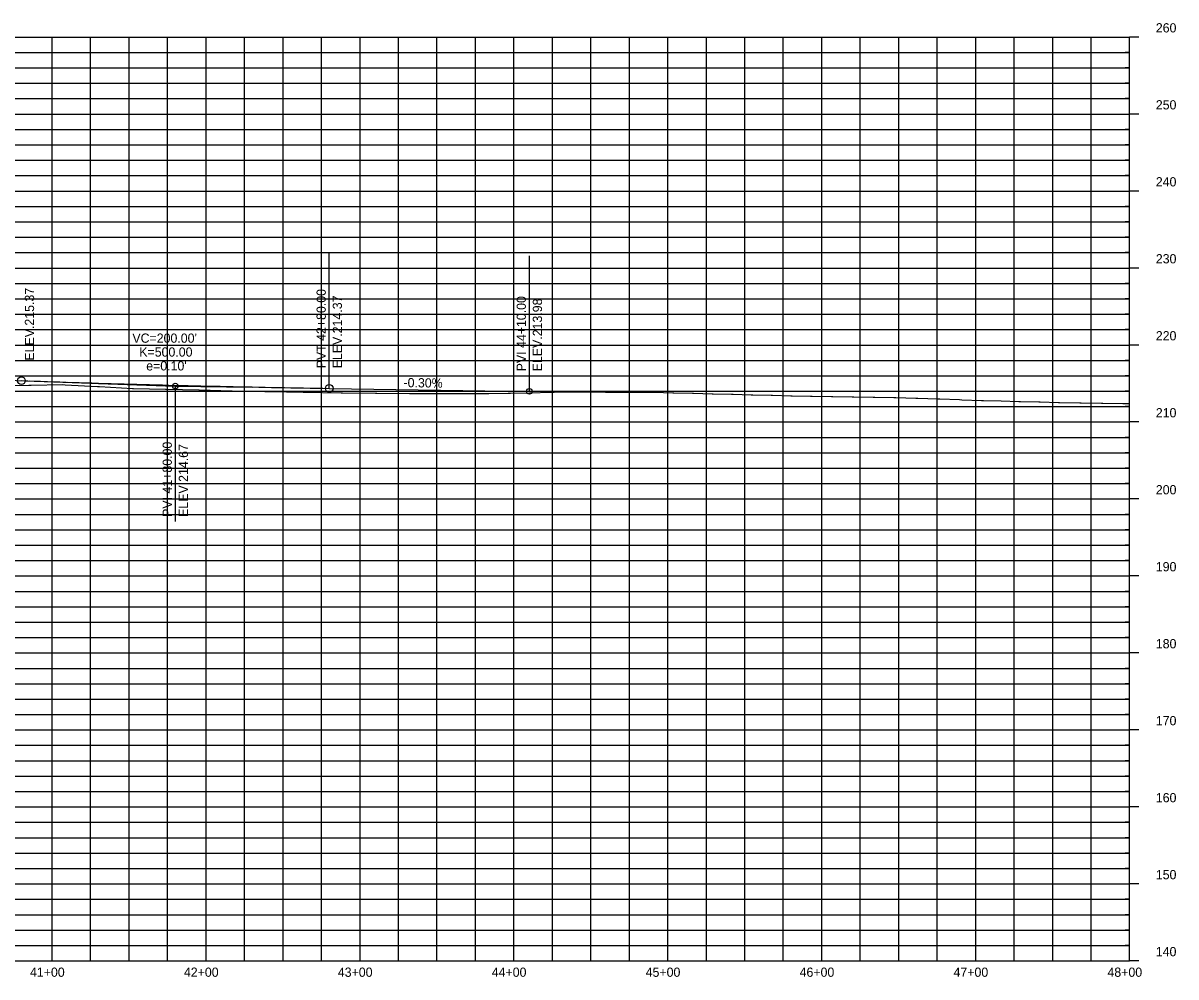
# Model space of a CAD drawing. Extents: x 1732967 to 1742744, y 374025 to 374739.
# Drawn here: x 1741995 to 1742744, y 374119 to 374739 of the extents above; entities that cross this region are included whole.
import ezdxf

# ---------------------------------------------------------------- set-up
doc = ezdxf.new("R2010")
doc.units = 0
for name, color, linetype in [('R_Axis_Annotation', 7, 'Continuous'), ('R_Exist Surface', 7, 'Continuous'), ('R_Grid', 7, 'Continuous'), ('R_Grid Annot', 7, 'Continuous'), ('R_Grid_Minor', 7, 'Continuous'), ('R_Horz Alg', 7, 'Continuous'), ('R_Vert Alg', 7, 'Continuous'), ('R_Vert Alg Annot', 7, 'Continuous')]:
    doc.layers.add(name, color=color, linetype=linetype)

msp = doc.modelspace()

# ---------------------------------------------------------------- linework, layer by layer
at = {"layer": 'R_Exist Surface'}
msp.add_lwpolyline([(1741978.17, 374503.33), (1741998.74, 374503.59), (1742000.16, 374503.6), (1742020.8, 374503.86), (1742022.27, 374503.78), (1742043.46, 374502.62), (1742044.55, 374502.55), (1742066.11, 374501.37), (1742066.76, 374501.37), (1742087.61, 374500.9), (1742088.06, 374500.89), (1742109.12, 374500.42), (1742109.33, 374500.41), (1742130.61, 374499.87), (1742130.91, 374499.86), (1742152.11, 374499.32), (1742166.14, 374499.13), (1742176.9, 374498.98), (1742177.22, 374498.98), (1742201.68, 374498.64), (1742202.62, 374498.63), (1742223.88, 374498.34), (1742224.73, 374498.33), (1742246.09, 374498.03), (1742246.53, 374498.03), (1742258.97, 374498.03), (1742259.56, 374498.03), (1742271.86, 374498.04), (1742272.61, 374498.03), (1742284.74, 374498.04), (1742285.65, 374498.03), (1742297.63, 374498.04), (1742310.16, 374498.3), (1742310.91, 374498.31), (1742311.64, 374498.32), (1742324.19, 374498.59), (1742324.6, 374498.59), (1742337.48, 374498.88), (1742337.55, 374498.88), (1742339.99, 374498.93), (1742350.54, 374499.14), (1742350.78, 374499.14), (1742364.11, 374499.1), (1742364.21, 374499.1), (1742373.37, 374499.07), (1742377.64, 374499.05), (1742377.7, 374499.05), (1742391.07, 374498.98), (1742391.31, 374498.98), (1742404.5, 374498.92), (1742404.9, 374498.91), (1742417.2, 374498.61), (1742417.74, 374498.59), (1742429.89, 374498.29), (1742430.57, 374498.27), (1742442.59, 374497.98), (1742443.4, 374497.96), (1742455.28, 374497.66), (1742456.25, 374497.65), (1742468.12, 374497.33), (1742469.07, 374497.31), (1742480.97, 374497), (1742481.89, 374496.98), (1742493.81, 374496.66), (1742494.7, 374496.65), (1742506.65, 374496.33), (1742507.56, 374496.32), (1742520.19, 374496.13), (1742521.18, 374496.12), (1742533.73, 374495.94), (1742534.8, 374495.93), (1742547.27, 374495.75), (1742548.41, 374495.73), (1742560.82, 374495.55), (1742562.09, 374495.51), (1742575.02, 374495.07), (1742576.35, 374495.03), (1742589.23, 374494.59), (1742590.62, 374494.55), (1742603.43, 374494.12), (1742604.88, 374494.07), (1742617.64, 374493.64), (1742618.99, 374493.61), (1742630.34, 374493.29), (1742642.02, 374492.97), (1742643.04, 374492.95), (1742654.9, 374492.62), (1742655.73, 374492.6), (1742667.77, 374492.27), (1742668.42, 374492.26), (1742681.65, 374492.06), (1742682.43, 374492.04), (1742695.58, 374491.84), (1742696.44, 374491.83), (1742709.52, 374491.63), (1742710.45, 374491.62), (1742713.91, 374491.57)], dxfattribs=at)
at = {"layer": 'R_Grid'}
for p, q in [((1739913.91, 374729.61), (1742713.91, 374729.61)), ((1742013.91, 374129.61), (1742013.91, 374729.61)), ((1742113.91, 374129.61), (1742113.91, 374729.61)), ((1742213.91, 374129.61), (1742213.91, 374729.61)), ((1742313.91, 374129.61), (1742313.91, 374729.61)), ((1742413.91, 374129.61), (1742413.91, 374729.61)), ((1742513.91, 374129.61), (1742513.91, 374729.61)), ((1742613.91, 374129.61), (1742613.91, 374729.61)), ((1742713.91, 374129.61), (1742713.91, 374729.61)), ((1739913.91, 374679.61), (1742713.91, 374679.61)), ((1739913.91, 374629.61), (1742713.91, 374629.61)), ((1739913.91, 374579.61), (1742713.91, 374579.61)), ((1739913.91, 374529.61), (1742713.91, 374529.61)), ((1739913.91, 374479.61), (1742713.91, 374479.61)), ((1739913.91, 374429.61), (1742713.91, 374429.61)), ((1739913.91, 374379.61), (1742713.91, 374379.61)), ((1739913.91, 374329.61), (1742713.91, 374329.61)), ((1739913.91, 374279.61), (1742713.91, 374279.61)), ((1739913.91, 374229.61), (1742713.91, 374229.61)), ((1739913.91, 374179.61), (1742713.91, 374179.61)), ((1739913.91, 374129.61), (1742713.91, 374129.61))]:
    msp.add_line(p, q, dxfattribs=at)
at = {"layer": 'R_Grid Annot'}
for p, q in [((1742719.91, 374729.61), (1742713.91, 374729.61)), ((1742719.91, 374729.61), (1742713.91, 374729.61)), ((1742713.91, 374719.61), (1742710.91, 374719.61)), ((1742713.91, 374709.61), (1742710.91, 374709.61)), ((1742713.91, 374699.61), (1742710.91, 374699.61)), ((1742713.91, 374689.61), (1742710.91, 374689.61)), ((1742719.91, 374679.61), (1742713.91, 374679.61)), ((1742713.91, 374669.61), (1742710.91, 374669.61)), ((1742713.91, 374659.61), (1742710.91, 374659.61)), ((1742713.91, 374649.61), (1742710.91, 374649.61)), ((1742713.91, 374639.61), (1742710.91, 374639.61)), ((1742719.91, 374629.61), (1742713.91, 374629.61)), ((1742713.91, 374619.61), (1742710.91, 374619.61)), ((1742713.91, 374609.61), (1742710.91, 374609.61)), ((1742713.91, 374599.61), (1742710.91, 374599.61)), ((1742713.91, 374589.61), (1742710.91, 374589.61)), ((1742719.91, 374579.61), (1742713.91, 374579.61)), ((1742713.91, 374569.61), (1742710.91, 374569.61)), ((1742713.91, 374559.61), (1742710.91, 374559.61)), ((1742713.91, 374549.61), (1742710.91, 374549.61)), ((1742713.91, 374539.61), (1742710.91, 374539.61)), ((1742719.91, 374529.61), (1742713.91, 374529.61)), ((1742713.91, 374519.61), (1742710.91, 374519.61)), ((1742713.91, 374509.61), (1742710.91, 374509.61)), ((1742713.91, 374499.61), (1742710.91, 374499.61)), ((1742713.91, 374489.61), (1742710.91, 374489.61)), ((1742719.91, 374479.61), (1742713.91, 374479.61)), ((1742713.91, 374469.61), (1742710.91, 374469.61)), ((1742713.91, 374459.61), (1742710.91, 374459.61)), ((1742713.91, 374449.61), (1742710.91, 374449.61)), ((1742713.91, 374439.61), (1742710.91, 374439.61)), ((1742719.91, 374429.61), (1742713.91, 374429.61)), ((1742713.91, 374419.61), (1742710.91, 374419.61)), ((1742713.91, 374409.61), (1742710.91, 374409.61)), ((1742713.91, 374399.61), (1742710.91, 374399.61)), ((1742713.91, 374389.61), (1742710.91, 374389.61)), ((1742719.91, 374379.61), (1742713.91, 374379.61)), ((1742713.91, 374369.61), (1742710.91, 374369.61)), ((1742713.91, 374359.61), (1742710.91, 374359.61)), ((1742713.91, 374349.61), (1742710.91, 374349.61)), ((1742713.91, 374339.61), (1742710.91, 374339.61)), ((1742719.91, 374329.61), (1742713.91, 374329.61)), ((1742713.91, 374319.61), (1742710.91, 374319.61)), ((1742713.91, 374309.61), (1742710.91, 374309.61)), ((1742713.91, 374299.61), (1742710.91, 374299.61)), ((1742713.91, 374289.61), (1742710.91, 374289.61)), ((1742719.91, 374279.61), (1742713.91, 374279.61)), ((1742713.91, 374269.61), (1742710.91, 374269.61)), ((1742713.91, 374259.61), (1742710.91, 374259.61)), ((1742713.91, 374249.61), (1742710.91, 374249.61)), ((1742713.91, 374239.61), (1742710.91, 374239.61)), ((1742719.91, 374229.61), (1742713.91, 374229.61)), ((1742713.91, 374219.61), (1742710.91, 374219.61)), ((1742713.91, 374209.61), (1742710.91, 374209.61)), ((1742713.91, 374199.61), (1742710.91, 374199.61)), ((1742713.91, 374189.61), (1742710.91, 374189.61)), ((1742719.91, 374179.61), (1742713.91, 374179.61)), ((1742713.91, 374169.61), (1742710.91, 374169.61)), ((1742713.91, 374159.61), (1742710.91, 374159.61)), ((1742713.91, 374149.61), (1742710.91, 374149.61)), ((1742713.91, 374139.61), (1742710.91, 374139.61)), ((1742719.91, 374129.61), (1742713.91, 374129.61))]:
    msp.add_line(p, q, dxfattribs=at)
at = {"layer": 'R_Grid_Minor'}
for p, q in [((1742038.91, 374129.61), (1742038.91, 374729.61)), ((1742063.91, 374129.61), (1742063.91, 374729.61)), ((1742088.91, 374129.61), (1742088.91, 374729.61)), ((1742138.91, 374129.61), (1742138.91, 374729.61)), ((1742163.91, 374129.61), (1742163.91, 374729.61)), ((1742188.91, 374129.61), (1742188.91, 374729.61)), ((1742238.91, 374129.61), (1742238.91, 374729.61)), ((1742263.91, 374129.61), (1742263.91, 374729.61)), ((1742288.91, 374129.61), (1742288.91, 374729.61)), ((1742338.91, 374129.61), (1742338.91, 374729.61)), ((1742363.91, 374129.61), (1742363.91, 374729.61)), ((1742388.91, 374129.61), (1742388.91, 374729.61)), ((1742438.91, 374129.61), (1742438.91, 374729.61)), ((1742463.91, 374129.61), (1742463.91, 374729.61)), ((1742488.91, 374129.61), (1742488.91, 374729.61)), ((1742538.91, 374129.61), (1742538.91, 374729.61)), ((1742563.91, 374129.61), (1742563.91, 374729.61)), ((1742588.91, 374129.61), (1742588.91, 374729.61)), ((1742638.91, 374129.61), (1742638.91, 374729.61)), ((1742663.91, 374129.61), (1742663.91, 374729.61)), ((1742688.91, 374129.61), (1742688.91, 374729.61)), ((1739913.91, 374719.61), (1742713.91, 374719.61)), ((1739913.91, 374709.61), (1742713.91, 374709.61)), ((1739913.91, 374699.61), (1742713.91, 374699.61)), ((1739913.91, 374689.61), (1742713.91, 374689.61)), ((1739913.91, 374669.61), (1742713.91, 374669.61)), ((1739913.91, 374659.61), (1742713.91, 374659.61)), ((1739913.91, 374649.61), (1742713.91, 374649.61)), ((1739913.91, 374639.61), (1742713.91, 374639.61)), ((1739913.91, 374619.61), (1742713.91, 374619.61)), ((1739913.91, 374609.61), (1742713.91, 374609.61)), ((1739913.91, 374599.61), (1742713.91, 374599.61)), ((1739913.91, 374589.61), (1742713.91, 374589.61)), ((1739913.91, 374569.61), (1742713.91, 374569.61)), ((1739913.91, 374559.61), (1742713.91, 374559.61)), ((1739913.91, 374549.61), (1742713.91, 374549.61)), ((1739913.91, 374539.61), (1742713.91, 374539.61)), ((1739913.91, 374519.61), (1742713.91, 374519.61)), ((1739913.91, 374509.61), (1742713.91, 374509.61)), ((1739913.91, 374499.61), (1742713.91, 374499.61)), ((1739913.91, 374489.61), (1742713.91, 374489.61)), ((1739913.91, 374469.61), (1742713.91, 374469.61)), ((1739913.91, 374459.61), (1742713.91, 374459.61)), ((1739913.91, 374449.61), (1742713.91, 374449.61)), ((1739913.91, 374439.61), (1742713.91, 374439.61)), ((1739913.91, 374419.61), (1742713.91, 374419.61)), ((1739913.91, 374409.61), (1742713.91, 374409.61)), ((1739913.91, 374399.61), (1742713.91, 374399.61)), ((1739913.91, 374389.61), (1742713.91, 374389.61)), ((1739913.91, 374369.61), (1742713.91, 374369.61)), ((1739913.91, 374359.61), (1742713.91, 374359.61)), ((1739913.91, 374349.61), (1742713.91, 374349.61)), ((1739913.91, 374339.61), (1742713.91, 374339.61)), ((1739913.91, 374319.61), (1742713.91, 374319.61)), ((1739913.91, 374309.61), (1742713.91, 374309.61)), ((1739913.91, 374299.61), (1742713.91, 374299.61)), ((1739913.91, 374289.61), (1742713.91, 374289.61)), ((1739913.91, 374269.61), (1742713.91, 374269.61)), ((1739913.91, 374259.61), (1742713.91, 374259.61)), ((1739913.91, 374249.61), (1742713.91, 374249.61)), ((1739913.91, 374239.61), (1742713.91, 374239.61)), ((1739913.91, 374219.61), (1742713.91, 374219.61)), ((1739913.91, 374209.61), (1742713.91, 374209.61)), ((1739913.91, 374199.61), (1742713.91, 374199.61)), ((1739913.91, 374189.61), (1742713.91, 374189.61)), ((1739913.91, 374169.61), (1742713.91, 374169.61)), ((1739913.91, 374159.61), (1742713.91, 374159.61)), ((1739913.91, 374149.61), (1742713.91, 374149.61)), ((1739913.91, 374139.61), (1742713.91, 374139.61))]:
    msp.add_line(p, q, dxfattribs=at)
at = {"layer": 'R_Horz Alg'}
for p, q in [((1741773.91, 374514.16), (1742093.91, 374502.96)), ((1741773.91, 374514.16), (1742093.91, 374502.96)), ((1741773.91, 374514.16), (1742093.91, 374502.96)), ((1741998.91, 374506.29), (1742093.91, 374502.96)), ((1741998.91, 374506.29), (1742093.91, 374502.96)), ((1742023.91, 374505.41), (1742093.91, 374502.96)), ((1742193.91, 374501.46), (1742323.91, 374499.51)), ((1742193.91, 374501.46), (1742323.91, 374499.51)), ((1742193.91, 374501.46), (1742323.91, 374499.51))]:
    msp.add_line(p, q, dxfattribs=at)
msp.add_lwpolyline([(1741993.91, 374506.46), (1741998.08, 374506.32), (1742002.24, 374506.18), (1742006.41, 374506.03), (1742010.58, 374505.89), (1742014.74, 374505.76), (1742018.91, 374505.62), (1742023.08, 374505.49), (1742027.24, 374505.35), (1742031.41, 374505.22), (1742035.58, 374505.09), (1742039.74, 374504.96), (1742043.91, 374504.84), (1742048.08, 374504.71), (1742052.24, 374504.59), (1742056.41, 374504.47), (1742060.58, 374504.35), (1742064.74, 374504.24), (1742068.91, 374504.12), (1742073.08, 374504.01), (1742077.24, 374503.89), (1742081.41, 374503.78), (1742085.58, 374503.68), (1742089.74, 374503.57), (1742098.08, 374503.36), (1742102.24, 374503.26), (1742106.41, 374503.16), (1742110.58, 374503.06), (1742114.74, 374502.96), (1742118.91, 374502.87), (1742123.08, 374502.78), (1742127.24, 374502.69), (1742131.41, 374502.6), (1742135.58, 374502.51), (1742139.74, 374502.42), (1742143.91, 374502.34), (1742148.08, 374502.26), (1742152.24, 374502.18), (1742156.41, 374502.1), (1742160.58, 374502.02), (1742164.74, 374501.94), (1742168.91, 374501.87), (1742173.08, 374501.8), (1742177.24, 374501.73), (1742181.41, 374501.66), (1742185.58, 374501.59), (1742189.74, 374501.53), (1742193.91, 374501.46)], dxfattribs=at)
at = {"layer": 'R_Vert Alg'}
msp.add_line((1742193.91, 374501.46), (1742323.91, 374499.51), dxfattribs=at)
msp.add_lwpolyline([(1741993.91, 374506.46), (1741998.08, 374506.32), (1742002.24, 374506.18), (1742006.41, 374506.03), (1742010.58, 374505.89), (1742014.74, 374505.76), (1742018.91, 374505.62), (1742023.08, 374505.49), (1742027.24, 374505.35), (1742031.41, 374505.22), (1742035.58, 374505.09), (1742039.74, 374504.96), (1742043.91, 374504.84), (1742048.08, 374504.71), (1742052.24, 374504.59), (1742056.41, 374504.47), (1742060.58, 374504.35), (1742064.74, 374504.24), (1742068.91, 374504.12), (1742073.08, 374504.01), (1742077.24, 374503.89), (1742081.41, 374503.78), (1742085.58, 374503.68), (1742089.74, 374503.57), (1742098.08, 374503.36), (1742102.24, 374503.26), (1742106.41, 374503.16), (1742110.58, 374503.06), (1742114.74, 374502.96), (1742118.91, 374502.87), (1742123.08, 374502.78), (1742127.24, 374502.69), (1742131.41, 374502.6), (1742135.58, 374502.51), (1742139.74, 374502.42), (1742143.91, 374502.34), (1742148.08, 374502.26), (1742152.24, 374502.18), (1742156.41, 374502.1), (1742160.58, 374502.02), (1742164.74, 374501.94), (1742168.91, 374501.87), (1742173.08, 374501.8), (1742177.24, 374501.73), (1742181.41, 374501.66), (1742185.58, 374501.59), (1742189.74, 374501.53), (1742193.91, 374501.46)], dxfattribs=at)
at = {"layer": 'R_Vert Alg Annot'}
for p, q in [((1742193.91, 374511.46), (1742193.91, 374589.46)), ((1742323.91, 374509.51), (1742323.91, 374587.51)), ((1742193.91, 374501.46), (1742193.91, 374511.46)), ((1742323.91, 374499.51), (1742323.91, 374509.51)), ((1742043.91, 374504.71), (1742093.91, 374502.96)), ((1742093.91, 374502.96), (1742143.91, 374502.21)), ((1742093.91, 374502.96), (1742093.91, 374492.96)), ((1742093.91, 374492.96), (1742093.91, 374414.96))]:
    msp.add_line(p, q, dxfattribs=at)
for centre, radius in [((1741993.91, 374506.46), 2.5), ((1742093.91, 374502.96), 1.85), ((1742193.91, 374501.46), 2.5), ((1742323.91, 374499.51), 1.85)]:
    msp.add_circle(centre, radius, dxfattribs=at)

# ---------------------------------------------------------------- texts
at = {"layer": 'R_Axis_Annotation'}
for s, p in [('260', (1742730.92, 374732.61)), ('260', (1742730.92, 374732.61)), ('250', (1742730.92, 374682.61)), ('240', (1742730.92, 374632.61)), ('230', (1742730.92, 374582.61)), ('220', (1742730.92, 374532.61)), ('210', (1742730.92, 374482.61)), ('200', (1742730.92, 374432.61)), ('190', (1742730.92, 374382.61)), ('180', (1742730.92, 374332.61)), ('170', (1742730.92, 374282.61)), ('160', (1742730.92, 374232.61)), ('150', (1742730.92, 374182.61)), ('140', (1742730.92, 374132.61)), ('41+00', (1741999.5, 374119.26)), ('42+00', (1742099.5, 374119.26)), ('43+00', (1742199.5, 374119.26)), ('44+00', (1742299.5, 374119.26)), ('45+00', (1742399.5, 374119.26)), ('46+00', (1742499.5, 374119.26)), ('47+00', (1742599.5, 374119.26)), ('48+00', (1742699.5, 374119.26))]:
    msp.add_text(s, height=6, dxfattribs=at).set_placement(p)
at = {"layer": 'R_Vert Alg Annot'}
for s, rotation, p in [('ELEV.215.37', 90, (1742002.16, 374519.46)), ('PVT 42+80.00', 90, (1742191.66, 374514.46)), ('ELEV.214.37', 90, (1742202.16, 374514.46)), ('PVI 44+10.00', 90, (1742321.66, 374512.51)), ('ELEV.213.98', 90, (1742332.16, 374512.51)), ('-0.30%', 359.14063, (1742242.13, 374502.24)), ('PVI 41+80.00', 90, (1742091.66, 374417.96)), ('ELEV.214.67', 90, (1742102.16, 374417.96))]:
    msp.add_text(s, height=6, rotation=rotation, dxfattribs=at).set_placement(p)
for s, p in [("VC=200.00'", (1742066.01, 374531.07)), ('K=500.00', (1742070.5, 374522.07)), ("e=0.10'", (1742075.01, 374513.07))]:
    msp.add_text(s, height=6, dxfattribs=at).set_placement(p)

doc.saveas('drawing.dxf')
